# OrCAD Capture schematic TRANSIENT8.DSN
size A
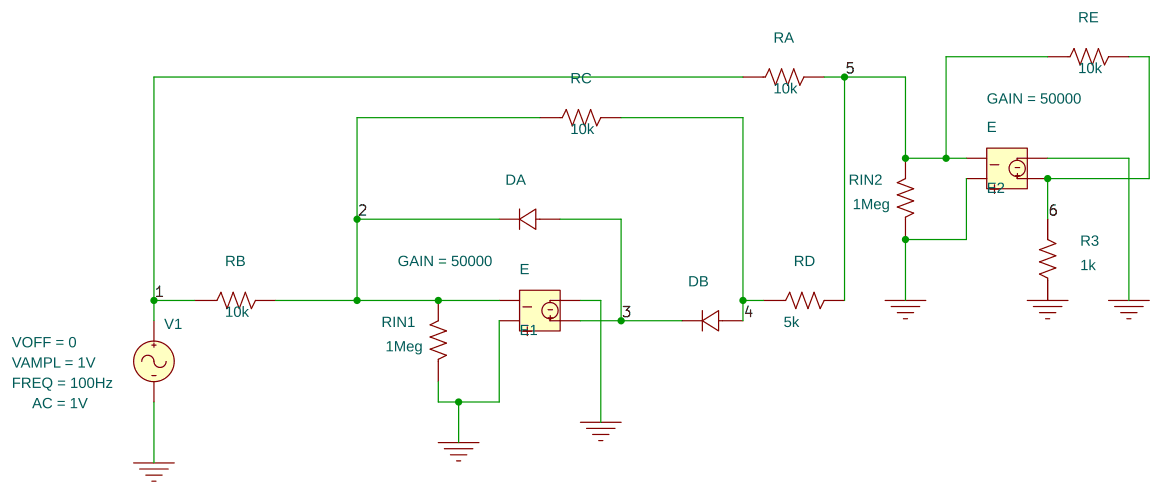
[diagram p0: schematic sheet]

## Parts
DA  Dbreak
DB  Dbreak
E1  E
E2  E
R3  1k  [AX/RC05]
RA  10k  [AX/RC05]
RB  10k  [AX/RC05]
RC  10k  [AX/RC05]
RD  5k  [AX/RC05]
RE  10k  [AX/RC05]
RIN1  1Meg  [AX/RC05]
RIN2  1Meg  [AX/RC05]
V1  VSIN

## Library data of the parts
DA DB = Dbreak
E1 E2 = E: GAIN: 50000
R3 RA RB RC RD RE RIN1 RIN2 = R
V1 = VSIN: AC: 1V; FREQ: 100Hz; VAMPL: 1V; VOFF: 0

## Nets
0: E1.1 E1.4 E2.1 E2.4 R3.1 RIN1.1 RIN2.1 V1.2(-)
1: RA.1 RB.1 V1.1(+)
2: DA.1(2) E1.2 RB.2 RC.1 RIN1.2
3: DA.0(1) DB.1(2) E1.3
4: DB.0(1) RC.2 RD.1
5: E2.2 RA.2 RD.2 RE.1 RIN2.2
6: E2.3 R3.2 RE.2
